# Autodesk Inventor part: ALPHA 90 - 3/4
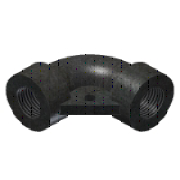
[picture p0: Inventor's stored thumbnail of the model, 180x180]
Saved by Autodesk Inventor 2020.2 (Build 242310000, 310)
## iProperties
Manager: www.cadconsulting.pl
Company: Fabian Stasiak CAD Consulting
Created: 2014-09
Part Number: ALPHA 90 - 3/4
Material: Stal
Description: Kolanko stalowe gwint. kąt 90, ALPHA
Document SubType Name: Modeling
Standard: ALPHA-010102
Designer: F.Stasiak
Manufacturer: ALPHA
Standards Organization: ANSI
Language: pl-PL
Size Designation: 3/4
Categories: <MemberInstance><Categories><Category DisplayName="Rury cienko- i grubościenne" InternalName="4347fa0f-2144-441d-94cd-e3e15c92b736" Mnemonic="TUBEANDPIPE"><Cate
Density: 7.85 g/cm^3
Appearance: Płyta
Catalog Web Link: www.expertbooks.pl
IsCustomPart: 0
Author: F.Stasiak
Subject: Zbiór ćwiczeń. Autodesk Inventor 2020. Kurs Professional
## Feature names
1. Przeciągnięcie1
2. Wyciągnięcie proste1 [Extrusion]
3. Wyciągnięcie proste2 [Extrusion]
4. Wyciągnięcie proste5 [Extrusion]
## Parameters: d0 = 59.182 mm, d1 = 59.182 mm, d2 = 29.591 mm, d4 = 0, d5 = 0, d6 = 38.1 mm, d7 = 23.6728 mm, d9 = 18.288 mm, d10 = 0, d11 = 38.1 mm, d12 = 18.288 mm, d13 = 0, d19 = 19.8628 mm, d20 = 0, d21 = 19.8628 mm, d22 = 0, ID = 23.6728 mm, OD = 38.1 mm, GL = 18.288 mm, G = 3.429 mm, d23 = 3.429 mm, d24 = 6.35 mm, d26 = 6.858 mm, d27 = 0
